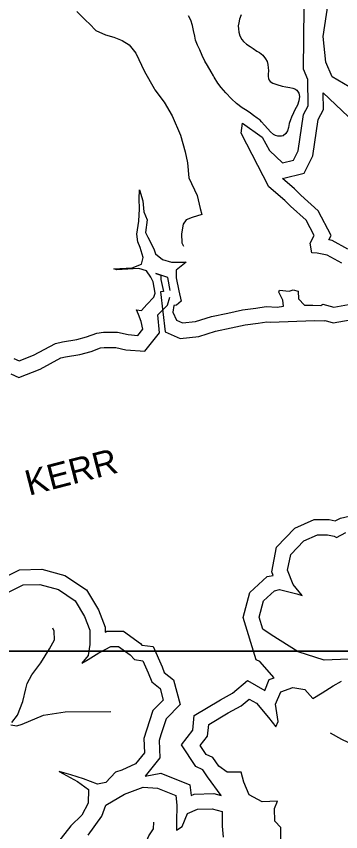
# Model space of a CAD drawing. Extents: x 1248089 to 1457196, y 820910 to 988753.
# Drawn here: x 1328755 to 1331201, y 867474 to 873625 of the extents above; entities that cross this region are included whole.
import ezdxf

# ---------------------------------------------------------------- set-up
doc = ezdxf.new("R2010")
doc.units = 0
for name, color, linetype in [('Exist Hydrographic Buffer Line', 7, 'Continuous'), ('Exist Hydrographic Reservoir', 7, 'Continuous'), ('Exist Hydrographic Reservoir Label', 7, 'Continuous'), ('Exist Road Non-System Type 51', 7, 'Continuous'), ('Exist Road Secondary Type 51 Attributed', 7, 'Continuous'), ('Map Preparation Inset Cut Line', 7, 'Continuous')]:
    doc.layers.add(name, color=color, linetype=linetype)

msp = doc.modelspace()

# ---------------------------------------------------------------- linework, layer by layer
at = {"layer": 'Exist Hydrographic Buffer Line'}
for points in [[(1331068.6, 873048.8), (1331352.9, 872779.1), (1331480.9, 872611.2), (1331584.3, 872329.4), (1331731, 872162.9), (1331955.4, 872168.1), (1332096.1, 872224.8), (1332197.2, 872321.2), (1332401, 872564.5), (1332659, 872628.9), (1332975.5, 872856.5), (1332979.6, 872776.7), (1333216.1, 872772.2), (1333407.6, 872906.8), (1333458, 873089.8)], [(1330852.5, 872323.6), (1330761, 872400.7), (1330924.3, 872442), (1330991.6, 872573.5), (1331031.4, 872847.2), (1331071.2, 872920.9), (1331068.6, 873048.8)], [(1331255.6, 871869.5), (1331136.7, 871933.6), (1331112, 871938.4), (1331128.9, 871972.3), (1331031.7, 872157.6), (1330900.7, 872275.9), (1330852.5, 872323.6)], [(1329914.7, 871557), (1329897.8, 871655.4), (1329807.7, 871684.2), (1329844.9, 871673.3), (1329844.9, 871639.8), (1329863.6, 871549), (1329843, 871546), (1329877.3, 871244), (1329991.1, 871194.2), (1330130.3, 871210.6), (1330256, 871249.5), (1330374.5, 871274.3), (1330480.1, 871296.6), (1330577.4, 871310.5), (1330643, 871320.2), (1330669.1, 871318.4), (1331005, 871331.5), (1331081, 871327.9), (1331083, 871329.1), (1331144.5, 871312.1), (1331315.1, 871344.1)], [(1328712.6, 870927.6), (1328774.1, 870901.2), (1328933.9, 870964.3), (1329089.2, 871048.9), (1329124.8, 871056.4), (1329234.4, 871074.1), (1329319.9, 871097.2), (1329389.7, 871123), (1329418.2, 871126.4), (1329504.6, 871126.3), (1329580.8, 871109.9), (1329723.3, 871098.9), (1329834.8, 871236.3), (1329822.2, 871372.7), (1329895.7, 871446.3), (1329912.3, 871507.3)], [(1330299.6, 867748), (1330196.8, 867889.2), (1330160.4, 867942.2), (1330107.3, 867966.7), (1330001.4, 868130.5), (1330086.2, 868239.7), (1330096.4, 868351.8), (1330295.5, 868470.2), (1330385.4, 868518.6), (1330496.8, 868615.2), (1330627.9, 868540.3), (1330662, 868622.2), (1330699.3, 868635.2), (1330590, 868759.1), (1330564, 868770.7), (1330466.6, 869091.2), (1330514.9, 869278.7), (1330647.1, 869398.4), (1330691.8, 869407.4), (1330680.4, 869435.4), (1330717.5, 869621), (1330855.5, 869764.6), (1331001.1, 869829), (1331113.7, 869829), (1331159.4, 869818.5), (1331199.7, 869838.7), (1331308.3, 869864.7)], [(1328609.1, 869367.7), (1328778.1, 869449.7), (1328947.3, 869455), (1329120.1, 869405.6), (1329283.4, 869298.3), (1329373.4, 869148.3), (1329424.2, 869016), (1329424.2, 868979), (1329438.1, 868986.3), (1329563.3, 868986.3), (1329690.7, 868893.5), (1329702, 868880.9), (1329787.5, 868870.2), (1329853.6, 868717.9), (1329870.7, 868676.4), (1329940.1, 868620), (1329991.1, 868432.9), (1329884.2, 868326), (1329845.4, 868206.1), (1329831.6, 868162), (1329836.5, 868031.6), (1329725.2, 867894.1), (1329845.3, 867915.1), (1330064.3, 867827.5), (1330073.1, 867748.1), (1330095.1, 867757.3), (1330244.1, 867762.6), (1330299.6, 867748)]]:
    msp.add_lwpolyline(points, dxfattribs=at)
at = {"layer": 'Exist Hydrographic Reservoir'}
for points in [[(1330778.5, 872235.8), (1330657.7, 872337.6), (1330449.7, 872742.3), (1330460.8, 872817.6), (1330607.7, 872712.8), (1330663.8, 872613.3), (1330761.8, 872519.4), (1330845.7, 872540.6), (1330880.7, 872608.9), (1330920.7, 872883.9), (1330955.8, 872948.9), (1330951.8, 873149.2), (1330919.8, 873225.3), (1330927.8, 873924.4), (1330913.7, 874016.6), (1330690.7, 874470.9)], [(1331416.7, 873061), (1331307.7, 873066.5), (1331135.7, 873168.4), (1331087.7, 873277.8), (1331067.7, 873471.7), (1331106.7, 873720.6), (1331076.7, 873862.3), (1330844.7, 874300.3), (1330723.7, 874470.1), (1330690.7, 874470.9)], [(1329801.6, 871537.5), (1329787.2, 871621), (1329769.9, 871658.4), (1329735.4, 871704.5), (1329677.9, 871721.8), (1329513.9, 871713.1), (1329490.9, 871718.9), (1329629, 871727.5), (1329698, 871756.3), (1329712.4, 871805.2), (1329689.4, 871880.1), (1329672.1, 871923.2), (1329663.5, 871980.8), (1329677.8, 872080.4), (1329683.6, 872172.5), (1329680.7, 872247.3), (1329683.6, 872316.4), (1329709.5, 872232.9), (1329715.2, 872149.4), (1329741.1, 872089), (1329729.6, 871994), (1329746.9, 871959.5), (1329792.9, 871870.2), (1329804.4, 871832.8), (1329856.2, 871789.7), (1329925.2, 871769.5), (1330034.5, 871769.5), (1329959.7, 871709.1), (1329959.7, 871651.5), (1329979.8, 871553.6), (1329997.1, 871475.9), (1329962.6, 871447.1), (1329942.4, 871444.3), (1329933.8, 871392.4), (1329962.6, 871332), (1330008.6, 871311.9), (1330106.4, 871323.4), (1330227.2, 871360.8), (1330350.9, 871386.7), (1330460.2, 871409.7), (1330560.8, 871424.1), (1330638.5, 871435.6), (1330720.9, 871429.9), (1330769.8, 871438.5), (1330764.1, 871484.6), (1330735.3, 871545), (1330738.2, 871559.4), (1330813, 871550.8), (1330841.7, 871562.3), (1330879.1, 871550.8), (1330882, 871493.2), (1330928, 871447.1), (1330991.3, 871447.1), (1331051.7, 871444.3), (1331066.1, 871452.9), (1331149.5, 871429.9), (1331287.5, 871455.8)], [(1331209.9, 871763.7), (1331097.7, 871824.2), (1331022.9, 871838.6), (1330982.7, 871841.5), (1330971.2, 871913.4), (1330999.9, 871971), (1330939.5, 872086.1), (1330821.6, 872192.6), (1330778.5, 872235.8)], [(1328735.6, 871042.6), (1328775.9, 871025.4), (1328885.2, 871068.5), (1329049.1, 871157.8), (1329103.8, 871169.3), (1329210.2, 871186.5), (1329285, 871206.7), (1329362.6, 871235.5), (1329411.5, 871241.2), (1329516.8, 871241.1), (1329597.3, 871223.8), (1329672.1, 871218), (1329709.5, 871264.1), (1329695.1, 871321.7), (1329675, 871376.4), (1329660.6, 871410.9), (1329698, 871405.1), (1329738.3, 871451.2), (1329792.9, 871505.9), (1329801.6, 871537.5)], [(1331259.5, 868776.5), (1331077.2, 868768.6), (1330879, 868832), (1330676.9, 868958.9), (1330613.5, 869002.6), (1330585.8, 869093.8), (1330617.5, 869216.7), (1330700.7, 869292), (1330740.3, 869300), (1330871.1, 869268.2), (1330910.7, 869256.4), (1330843.4, 869339.6), (1330799.8, 869446.7), (1330823.6, 869565.7), (1330922.6, 869668.8), (1331025.3, 869714.2), (1331100.6, 869714.2), (1331152.1, 869702.3), (1331168, 869694.4), (1331239.3, 869730.1)], [(1328675.4, 869272.3), (1328806.2, 869335.7), (1328933, 869339.7), (1329071.7, 869300), (1329198.5, 869216.7), (1329269.8, 869097.8), (1329309.4, 868994.7), (1329309.4, 868887.6), (1329297.5, 868804.3), (1329250, 868744.8), (1329297.5, 868772.6), (1329376.8, 868824.1), (1329466.5, 868871.4), (1329525.9, 868871.4), (1329613.1, 868808), (1329644.8, 868772.3), (1329708.2, 868764.4), (1329747.9, 868673.2), (1329775.6, 868605.8), (1329839, 868554.2), (1329862.8, 868467), (1329783.5, 868387.6), (1329736, 868240.9), (1329716.2, 868177.5), (1329720.1, 868070.4), (1329652.7, 867987.1), (1329549.7, 867939.5), (1329502.2, 867923.7), (1329430.8, 867844.4), (1329367.4, 867832.5), (1329260.4, 867872.1), (1329165.3, 867903.8), (1329078.2, 867927.6), (1329216.9, 867852.3), (1329300.1, 867792.8), (1329296.1, 867689.7), (1329248.6, 867598.5), (1329165.3, 867519.2), (1329066.2, 867389.5)], [(1330704.8, 867553.4), (1330700.8, 867648.5), (1330724.6, 867704.1), (1330609.7, 867700.1), (1330510.6, 867751.6), (1330471, 867846.8), (1330451.2, 867922.2), (1330344.2, 867922.2), (1330280.8, 867969.7), (1330237.2, 868033.2), (1330185.7, 868057), (1330142.1, 868124.4), (1330197.6, 868195.8), (1330205.5, 868283), (1330352.1, 868370.3), (1330451.1, 868423.6), (1330510.5, 868475.1), (1330566, 868443.4), (1330657.1, 868336.3), (1330712.6, 868265), (1330728.5, 868304.6), (1330708.6, 868435.5), (1330748.3, 868530.6), (1330839.4, 868562.4), (1330930.6, 868546.5), (1330990, 868479.1), (1331061.3, 868522.7), (1331144.5, 868574.3), (1331207.9, 868610)], [(1329296, 867449), (1329399, 867591.8), (1329430.7, 867675), (1329569.4, 867758.3), (1329712.1, 867809.9), (1329819.1, 867801.9), (1329957.8, 867746.4), (1329965.7, 867675), (1329961.7, 867548.1), (1329961.7, 867484.7), (1330005.3, 867512.4), (1330045, 867611.6), (1330120.3, 867643.3), (1330231.2, 867647.3), (1330306.5, 867627.4), (1330306.5, 867516.4), (1330314.4, 867433.1)], [(1330748.4, 867402.7), (1330748.4, 867505.8), (1330704.8, 867553.4)]]:
    msp.add_lwpolyline(points, dxfattribs=at)
at = {"layer": 'Exist Road Non-System Type 51'}
for points in [[(1330246.7, 873164.9), (1330240.5, 873174.6), (1330223.1, 873205.2), (1330196.3, 873253.7), (1330177.1, 873286.1), (1330156, 873328.8), (1330139, 873371.2), (1330121.9, 873407.5), (1330106.7, 873446.1), (1330101.5, 873476.2), (1330090.3, 873518.4), (1330083.3, 873556.6), (1330070.3, 873596.9), (1330052.9, 873629.4)], [(1330451.3, 873636.1), (1330438.7, 873604.3), (1330431.9, 873576.4), (1330427.4, 873552.7), (1330429, 873530.6), (1330432.3, 873504.4), (1330439.7, 873478.2), (1330455, 873449.9), (1330468.7, 873433.6), (1330490.3, 873414.9), (1330517.9, 873396.4), (1330541.5, 873381.9), (1330569.1, 873363.1), (1330588.9, 873350.7), (1330612.5, 873332), (1330633.8, 873303.6), (1330645.4, 873283.4), (1330650.7, 873261.2), (1330654.2, 873235.1), (1330655.8, 873215.1), (1330653, 873185.1), (1330654.7, 873171.1), (1330656.4, 873155.1), (1330662.2, 873142.9), (1330669.8, 873132.6), (1330689.5, 873120.2), (1330719.3, 873109.6), (1330759.1, 873098.6), (1330787, 873092), (1330816.9, 873087.2), (1330838.9, 873082.7), (1330854.8, 873078.4), (1330870.4, 873067.9), (1330885.9, 873045.6), (1330889.4, 873019.5), (1330884.6, 872987.6), (1330873.9, 872955.8), (1330855, 872920.1), (1330844.5, 872896.5), (1330829.7, 872862.8), (1330821.3, 872845), (1330812.5, 872817.1), (1330807.9, 872787.2), (1330799.2, 872761.3), (1330786.8, 872741.6), (1330766.4, 872724.2), (1330754.4, 872720.4), (1330726.3, 872721), (1330708.4, 872725.5), (1330694.6, 872733.8), (1330671, 872754.3), (1330651.6, 872774.9), (1330626.1, 872803.4), (1330604.6, 872827.9), (1330593.1, 872840.3), (1330571.4, 872856.8), (1330543.8, 872877.3), (1330520.3, 872894), (1330496.6, 872912.5), (1330457.1, 872935.5), (1330415.9, 872966.6), (1330378.5, 873001.3), (1330333.6, 873046.5), (1330298.6, 873087.2), (1330275.3, 873119.9), (1330246.7, 873164.9)], [(1329799.6, 873070.9), (1329870, 872976), (1329930.9, 872874.4), (1329991.8, 872728.1), (1330028.3, 872602.1), (1330044.6, 872520.8), (1330056.8, 872407), (1330117.7, 872272.9), (1330142.1, 872175.3), (1330154.3, 872130.6)], [(1330154.3, 872130.6), (1330081.1, 872106.2), (1330036.5, 872090), (1330012.1, 872057.5), (1329999.9, 871984.3), (1330004, 871915.2), (1330016.2, 871890.8)], [(1328719.8, 868298.4), (1328764.3, 868354), (1328803.2, 868456.9), (1328825.4, 868551.4), (1328836.5, 868593.1), (1328872.6, 868657), (1328939.3, 868748.7), (1329005.9, 868854.3), (1329042, 868921.1), (1329039.3, 868987.8), (1329030.9, 869010)], [(1328712.3, 868279.7), (1328758.7, 868273.4), (1328797.6, 868284.5), (1328958.7, 868354), (1329122.6, 868379), (1329467, 868381.8)], [(1332301.5, 867579.3), (1332223.9, 867630.7), (1332114, 867779.9), (1332009.4, 867942.2), (1331957.1, 867997.2), (1331876, 868052.2), (1331805.3, 868078.4), (1331739.9, 868091.5), (1331682.4, 868088.8), (1331624.8, 868067.9), (1331538.5, 868075.7), (1331436.5, 868088.8), (1331300.4, 868128.1), (1331208.9, 868170), (1331125.1, 868217.1)], [(1329700.3, 867328.4), (1329730.9, 867389.5), (1329753.1, 867442.3), (1329789.2, 867495.1), (1329792, 867545.2)]]:
    msp.add_lwpolyline(points, dxfattribs=at)
at = {"layer": 'Exist Road Secondary Type 51 Attributed'}
msp.add_lwpolyline([(1329211.2, 873662), (1329279.5, 873593.6), (1329306.5, 873568.4), (1329354.5, 873518.5), (1329426.4, 873486.1), (1329491.2, 873468.1), (1329552.3, 873442.9), (1329606.3, 873410.5), (1329656.7, 873345.7), (1329721.4, 873208.9), (1329793.4, 873079.3), (1329799.6, 873070.9)], dxfattribs=at)
at = {"layer": 'Map Preparation Inset Cut Line'}
for points in [[(1313026.2, 913085.2), (1388709.5, 913085.2), (1388709.5, 884379.9), (1373500.6, 884376.6), (1373500.6, 868836.7), (1313026.2, 868836.7)], [(1313026.2, 824588.2), (1313026.2, 868836.7), (1388709.5, 868836.7), (1388709.5, 835631.5), (1373500.6, 835631.5), (1373500.6, 824588.2)]]:
    msp.add_lwpolyline(points, close=True, dxfattribs=at)

# ---------------------------------------------------------------- texts
at = {"layer": 'Exist Hydrographic Reservoir Label'}
msp.add_text('KERR ', height=190, rotation=14.51992, dxfattribs=at).set_placement((1328849.8, 870008.2))

doc.saveas('drawing.dxf')
